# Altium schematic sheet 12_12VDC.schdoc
size 302 x 215 mm; Symbol: Sheet_A4; Device: Sheet_A4; @Project Name: Avaota A1; @Page No: 2; @Page Count: 13; @Update Date: 2024-04-06
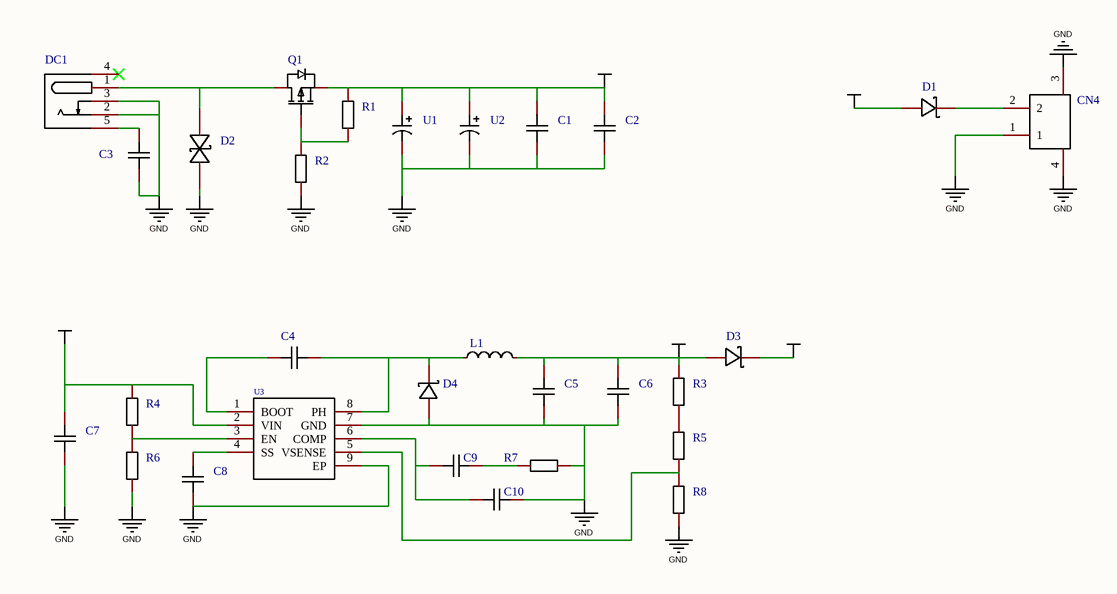
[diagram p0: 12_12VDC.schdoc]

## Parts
C1  CAP_0603  [C0603-NSK]  (value not drawn)
C2  CAP_0603  [C0603-NSK]  (value not drawn)
C3  CAP_0603  [C0603-NSK]  (value not drawn)
C4  CAP_0402  [c0402-nsk]  (value not drawn)
C5  CAP_0805  [C0805 NSK]  (value not drawn)
C6  CAP_0805  [C0805 NSK]  (value not drawn)
C7  CAP_0603  [C0603-NSK]  (value not drawn)
C8  CAP_0603  [C0603-NSK]  (value not drawn)
C9  CAP_0402  [c0402-nsk]  (value not drawn)
C10  CAP_0402  [c0402-nsk]  (value not drawn)
CN4  0533980271  [CONN-SMD_2P-P1.25_053398-0X71]  (value not drawn)
D1  B5819WS_C22624  [SOD-323_L1.8-W1.3-LS2.5-RD]  (value not drawn)
D2  SMCJ15CA_C438202  [SMC_L6.9-W5.9-LS7.9-BI]  (value not drawn)
D3  SS54_C22452  [SMA_L4.4-W2.8-LS5.4-R-RD]  (value not drawn)
D4  SS54_C22452  [SMA_L4.4-W2.8-LS5.4-R-RD]  (value not drawn)
DC1  DC-044A-A200  [DC-IN-TH_DC-044A-20A]  (value not drawn)
L1  FXL0630-4R7-M  [IND-SMD_L7.0-W6.6]  (value not drawn)
Q1  YJL2305A  [SOT-23-3_L2.9-W1.3-P1.90-LS2.4-BR]  (value not drawn)
R1  Res_0603  [R0603 NSK]  (value not drawn)
R2  Res_0603  [R0603 NSK]  (value not drawn)
R3  Res_0402  [R0402-NSK]  (value not drawn)
R4  Res_0402  [R0402-NSK]  (value not drawn)
R5  Res_0402  [R0402-NSK]  (value not drawn)
R6  Res_0402  [R0402-NSK]  (value not drawn)
R7  Res_0402  [R0402-NSK]  (value not drawn)
R8  Res_0402  [R0402-NSK]  (value not drawn)
U1  RVT1H101M0607  [CAP-SMD_BD6.3-L6.6-W6.6-LS7.6-RD]  (value not drawn)
U2  RVT1H101M0607  [CAP-SMD_BD6.3-L6.6-W6.6-LS7.6-RD]  (value not drawn)
U3  TPS54531DDAR  [SOIC-8_L5.0-W4.0-P1.27-LS6.0-BL-EP2.0]  (value not drawn)

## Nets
DCIN-5V: C5.2 C6.2 D3.1(A) L1.2 R3.2
DCIN-12V: C1.2 C2.2 C7.2 Q1.2(S) R1.2 R4.2 U1.1 U2.1 U3.2(VIN)
GND: C1.1 C2.1 C3.1 C5.1 C6.1 C7.1 C8.1 C10.2 CN4.1 CN4.3 CN4.4 D2.1 D4.1(A) DC1.2 DC1.3 R2.1 R6.1 R7.2 R8.1 U1.2 U2.2 U3.7(GND) U3.9(EP)
VBUS: D1.2(A) D3.2(K)
NetC3_2: C3.2 DC1.5
NetC4_1: C4.1 U3.1(BOOT)
NetC4_2: C4.2 D4.2(K) L1.1 U3.8(PH)
NetC8_2: C8.2 U3.4(SS)
NetC9_1: C9.1 C10.1 U3.6(COMP)
NetC9_2: C9.2 R7.1
NetCN4_2: CN4.2 D1.1(K)
NetD2_2: D2.2 DC1.1 Q1.3(D)
NetQ1_1: Q1.1(G) R1.1 R2.2
NetR3_1: R3.1 R5.2
NetR4_1: R4.1 R6.2 U3.3(EN)
NetR5_1: R5.1 R8.2 U3.5(VSENSE)

Not connected (* = marked no-connect by the designer): DC1 4*

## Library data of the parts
C1-C3 C7 C8 = CAP_0603: Symbol: CapAcitance; Convert to PCB: yes; Value: 100nF
C4 = CAP_0402: Symbol: CapAcitance; Convert to PCB: yes; Value: 100nF
C5 C6 = CAP_0805: Symbol: CapAcitance; Convert to PCB: yes; Value: 47uF
C9 = CAP_0402: Symbol: CapAcitance; Convert to PCB: yes; Value: 2200pF
C10 = CAP_0402: Symbol: CapAcitance; Convert to PCB: yes; Value: 22pF
CN4 = 0533980271: Manufacturer: MOLEX; Add into BOM: yes; Pins Structure: 1x2P; Pitch: 1.25mm; Number of PINs Per Row: 2; Description: 插针结构:1x2P;间距:1.25mm;安装方式:立贴;参考系列:-;总PIN数:2P;排数:1;每排PIN数:2;行距:-;额定电流:-;触头材质:磷青铜;触头镀层:锡;工作温度范围:-;
D1 = B5819WS_C22624: Manufacturer: CJ(江苏长电/长晶); Add into BOM: yes; Forward Voltage (Vf@If): 600mV@1A; Reverse Voltage (Vr): 40V; Average Rectified Current (Io): 1A; Description: 正向压降(Vf):600mV@1A;直流反向耐压(Vr):40V;平均整流电流(Io):1A;
D2 = SMCJ15CA_C438202: Manufacturer: 晶导微电子; Add into BOM: yes
D3 D4 = SS54_C22452: Manufacturer Part: SS54; Manufacturer: MDD; Add into BOM: yes; Forward Voltage (Vf@If): 550mV@5A; Reverse Voltage (Vr): 40V; Average Rectified Current (Io): 5A; Reverse Leakage Current (Ir): 1mA@40V; Description: 正向压降(Vf):550mV@5A;直流反向耐压(Vr):40V;平均整流电流(Io):5A;
DC1 = DC-044A-A200: Manufacturer: XUNPU(讯普); Add into BOM: yes; Connector Type: DC电源插座; Inside Contact Diameter: 2mm; Outside Contact Diameter: 5.9mm; Current Rating (Max): 3A; Voltage Rating (Max): 30V; Description: 连接器类型:DC电源插座;安装方式:弯插;触点内径:2mm;触点外径:5.9mm;额定电流:3A;额定电压:30V;工作温度范围:-20℃~+70℃;
L1 = FXL0630-4R7-M: Manufacturer: cjiang(长江微电); Add into BOM: yes; Value: 4.7uH; Tolerance: ±20%; Rated Current: 6A; Saturation Current (Isat): 9A; DC Resistance (DCR): 33mΩ; Type: 一体成型电感; Description: 电感值:4.7uH;精度:±20%;额定电流:6A;饱和电流(Isat):9A;类型:一体成型电感;
Q1 = YJL2305A: Manufacturer: YANGJIE(扬杰); Add into BOM: yes; Type: P沟道; Drain Source Voltage (Vdss): 15V; Continuous Drain Current (Id): 5.6A; Power Dissipation (Pd): 1.2W; Drain Source On Resistance (RDS(on)@Vgs,Id): 25mΩ@4.5V,5.6A; Gate Threshold Voltage (Vgs(th)@Id): 1V@250uA; Total Gate Charge (Qg@Vgs): 7.2nC@4.5V; Input Capacitance (Ciss@Vds): 890pF@9V; Reverse Transfer Capacitance (Crss@Vds): 85pF@9V; Description: 类型:P沟道;漏源电压(Vdss):15V;连续漏极电流(Id):5.6A;功率(Pd):1.2W;导通电阻(RDS(on)@Vgs,Id):25mΩ@4.5V,5.6A;阈值电压(Vgs(th)@Id):1V@250uA;
R1 R2 = Res_0603: Symbol: 电阻; Convert to PCB: yes; Value: 100K
R3 = Res_0402: Symbol: 电阻; Convert to PCB: yes; Value: 51.1
R4 = Res_0402: Symbol: 电阻; Convert to PCB: yes; Value: 665K
R5 = Res_0402: Symbol: 电阻; Convert to PCB: yes; Value: 10.2K
R6 = Res_0402: Symbol: 电阻; Convert to PCB: yes; Value: 130K
R7 = Res_0402: Symbol: 电阻; Convert to PCB: yes; Value: 37.4K
R8 = Res_0402: Symbol: 电阻; Convert to PCB: yes; Value: 1.96K
U1 U2 = RVT1H101M0607: Manufacturer: ROQANG(容强); Add into BOM: yes; Value: 100uF; Tolerance: ±20%; Rated Voltage: 50V; Ripple Current: 229mA@120Hz; φD: 6.3mm; L: 7.7mm; Lifetime @ Temp: 2000hrs@105℃; Description: 容值:100uF;精度:±20%;额定电压:50V;纹波电流:229mA@120Hz;
U3 = TPS54531DDAR: Manufacturer: TI(德州仪器); Add into BOM: yes; Function: 降压型; Output Type: 可调; Input Voltage: 3.5V~28V; Output Voltage: 800mV~26.04V; Output Current (Max): 5A; Switching Frequency: 570kHz; Synchronous Rectification: 否; Number of Outputs: 1; Topology: 降压式; Switch tube (built-in/external): 内置; Description: 功能类型:降压型;输出类型:可调;输入电压:3.5V~28V;输出电压:800mV~26.04V;输出电流(最大值):5A;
